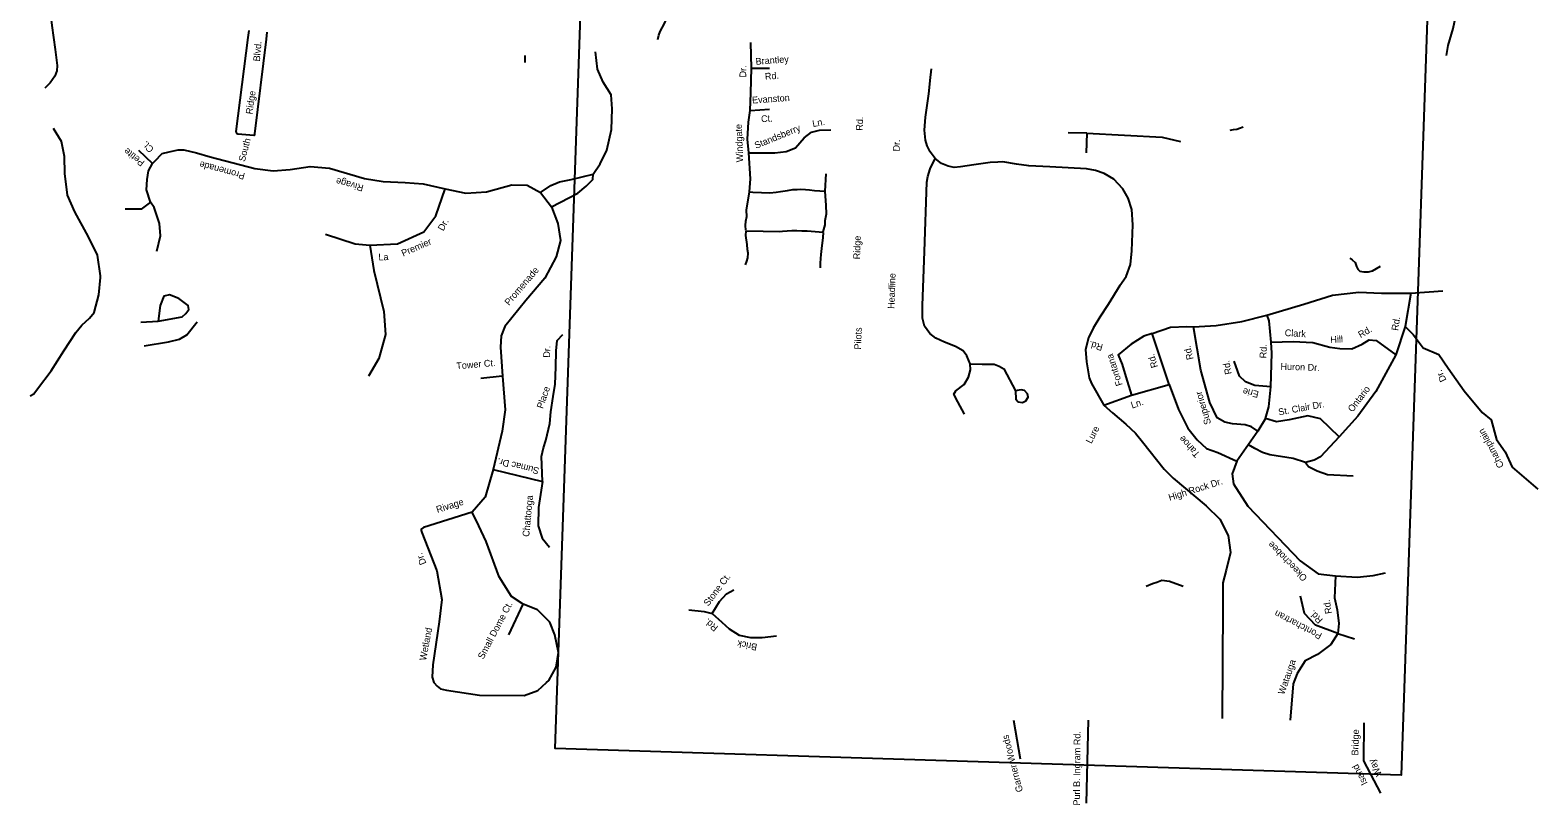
# Model space of a CAD drawing. Extents: x 2308163 to 2335412, y -96774 to 125428.
# Drawn here: x 2321191.5 to 2321648.5, y 52502.5 to 52737.2 of the extents above; entities that cross this region are included whole.
import ezdxf

# ---------------------------------------------------------------- set-up
doc = ezdxf.new("R2010")
doc.units = 0
for name, color, linetype in [('Old_Level_10', 7, 'Continuous'), ('Old_Level_35', 7, 'Continuous'), ('Old_Level_63', 7, 'Continuous')]:
    doc.layers.add(name, color=color, linetype=linetype)

msp = doc.modelspace()

# ---------------------------------------------------------------- linework, layer by layer
at = {"layer": 'Old_Level_35'}
for p, q in [((2321257.61, 52734.96), (2321257.88, 52737.07)), ((2321263.3, 52736.53), (2321263.04, 52734.43)), ((2321341.6, 52727.4), (2321341.53, 52729.52)), ((2321432.45, 52688.45), (2321432.83, 52693.65))]:
    msp.add_line(p, q, dxfattribs=at)
for points in [[(2321381.82, 52734.39), (2321382.04, 52735.64), (2321382.46, 52736.76), (2321383.77, 52739.18), (2321385.41, 52742.99), (2321387.8, 52749.06), (2321390, 52755.31), (2321393.51, 52763.8)], [(2321197.11, 52746.37), (2321197.22, 52745.37), (2321198.07, 52738.63), (2321199.11, 52731.32), (2321199.7, 52726.46), (2321199.64, 52724.83), (2321199.03, 52723.26), (2321197.54, 52721.2), (2321195.98, 52719.62)], [(2321620.88, 52729.51), (2321621.34, 52732.56), (2321622.81, 52737.7), (2321623.65, 52741.57), (2321623.84, 52743.45)], [(2321263.04, 52734.43), (2321259.55, 52705.75), (2321259.53, 52705.48), (2321259.5, 52705.38), (2321259.46, 52705.3), (2321259.39, 52705.27), (2321259.29, 52705.25), (2321254.41, 52705.68), (2321254.22, 52705.79), (2321254.13, 52705.93), (2321254.05, 52706.12), (2321254.02, 52706.27), (2321254, 52706.49), (2321257.61, 52734.96)], [(2321409.58, 52688.15), (2321409.89, 52692.15), (2321409.34, 52700.04), (2321408.98, 52704.19), (2321409.26, 52709.33), (2321409.78, 52712.84), (2321409.97, 52718.19), (2321410.12, 52725.65), (2321409.95, 52733.47)], [(2321349.58, 52683.67), (2321357.54, 52687.82), (2321360.04, 52689.96), (2321362.12, 52691.9), (2321362.18, 52693.52), (2321364.31, 52696.67), (2321366.27, 52700.84), (2321367.7, 52707.05), (2321367.91, 52713.3), (2321367.65, 52717.55), (2321365.16, 52721.47), (2321363.48, 52725.36), (2321362.91, 52730.61)], [(2321410.12, 52725.65), (2321415.58, 52725.66)], [(2321465.81, 52698.28), (2321464.31, 52700.34), (2321463.46, 52702.15), (2321462.91, 52703.87), (2321462.58, 52706.85), (2321462.93, 52710.83), (2321463.93, 52717.86), (2321464.43, 52722.85), (2321464.58, 52724.52), (2321464.69, 52725.45)], [(2321409.78, 52712.84), (2321415.65, 52713.25)], [(2321212.84, 52662.75), (2321211.97, 52668.96), (2321209.2, 52674.54), (2321205.01, 52682.09), (2321202.82, 52687.2), (2321202, 52693.74), (2321201.89, 52698.93), (2321201, 52703.4), (2321198.62, 52707.34)], [(2321409.34, 52700.04), (2321417.26, 52699.97), (2321420.72, 52700.44), (2321423.52, 52701.52), (2321426.15, 52704.56), (2321428.32, 52706.29), (2321430.8, 52706.89), (2321434.22, 52706.96)], [(2321511.82, 52705.95), (2321506.17, 52706.07)], [(2321511.82, 52705.95), (2321511.57, 52700)], [(2321511.82, 52705.95), (2321534.69, 52704.74), (2321540.22, 52703.4)], [(2321555.27, 52706.86), (2321556.31, 52707.06), (2321557.27, 52707.22), (2321558.12, 52707.49), (2321559.2, 52707.91)], [(2321228.64, 52696.76), (2321224.48, 52700.76)], [(2321227.94, 52685.09), (2321226.74, 52688.83), (2321226.99, 52691.93), (2321227.38, 52694.59), (2321228.64, 52696.76), (2321229.26, 52697.48), (2321231.56, 52699.77), (2321233.65, 52700.29), (2321236.34, 52700.94), (2321238.12, 52700.88), (2321241.94, 52700.01), (2321246.05, 52698.83)], [(2321246.05, 52698.83), (2321259.63, 52695.26), (2321265.15, 52694.58), (2321270.34, 52695.01), (2321276.4, 52695.91), (2321282.29, 52695.34), (2321292.9, 52692.27), (2321298.5, 52691.33), (2321305.14, 52690.98), (2321310.67, 52690.67), (2321317.26, 52689.09), (2321323.62, 52687.76), (2321329.79, 52688.16), (2321337.5, 52690.36), (2321342.17, 52690.2), (2321346.16, 52687.97), (2321349.58, 52683.67), (2321351.5, 52678.56), (2321352.31, 52673.48), (2321350.91, 52668.49), (2321347.48, 52662.08), (2321341.71, 52655.27), (2321335.4, 52647.37), (2321334.32, 52644.57), (2321334.08, 52641.14), (2321334.64, 52632.38), (2321335.52, 52622.14), (2321334.56, 52615.65), (2321331.82, 52604.06), (2321329.43, 52595.65), (2321325.46, 52591.11), (2321310.77, 52586.45), (2321310.01, 52585.98), (2321310, 52585.61), (2321310.23, 52584.99), (2321314.75, 52573.39), (2321316.3, 52564.73), (2321315.45, 52557.87), (2321313.52, 52544.89), (2321313.4, 52541.2), (2321313.83, 52539.59), (2321314.9, 52538.44), (2321315.86, 52537.67), (2321317.69, 52537.24), (2321327.73, 52535.66), (2321341.27, 52535.57), (2321345.39, 52537.15), (2321348.06, 52539.51), (2321348.7, 52540.11), (2321350.93, 52544.21), (2321351.7, 52548.62), (2321350.53, 52553.95), (2321349.06, 52557.81), (2321345.25, 52561.51), (2321341, 52563.26), (2321337.38, 52565.6), (2321333.65, 52571.51), (2321329.71, 52582.23), (2321327.53, 52586.98), (2321325.46, 52591.11)], [(2321476.5, 52636.13), (2321475.45, 52638.55), (2321474.36, 52640.02), (2321471.96, 52641.35), (2321468.63, 52642.61), (2321466.01, 52643.87), (2321464.21, 52645.29), (2321462.65, 52647.46), (2321461.97, 52649.88), (2321461.99, 52653.74), (2321462.61, 52670.14), (2321463.34, 52691.08), (2321463.61, 52692.81), (2321464.29, 52695.18), (2321465.81, 52698.28)], [(2321521.83, 52659.78), (2321523.73, 52662.53), (2321525.03, 52666.18), (2321525.41, 52670.32), (2321525.76, 52678.15), (2321525.45, 52682.87), (2321524.39, 52686.28), (2321522.76, 52689.08), (2321519.96, 52692.08), (2321517.11, 52693.75), (2321514.4, 52694.7), (2321511.67, 52695.19), (2321500.63, 52695.81), (2321494.28, 52696.1), (2321490.53, 52696.63), (2321486.39, 52697.24), (2321484.87, 52697.22), (2321482.51, 52697.06), (2321477.52, 52696.42), (2321473.51, 52695.74), (2321471.56, 52695.57), (2321469.78, 52695.95), (2321467.77, 52696.75), (2321465.81, 52698.28)], [(2321346.16, 52687.97), (2321349.34, 52690.13), (2321352, 52691.24), (2321355.46, 52691.93), (2321362.18, 52693.52)], [(2321281.04, 52675.42), (2321290.04, 52672.41), (2321294.46, 52672.01), (2321302.85, 52672.46), (2321310.86, 52676.12), (2321314.47, 52680.92), (2321317.26, 52689.09)], [(2321408.49, 52676.57), (2321408.39, 52677.95), (2321408.44, 52679.33), (2321408.74, 52680.75), (2321408.7, 52682.67), (2321409.58, 52688.15)], [(2321409.58, 52688.15), (2321410.62, 52688.12), (2321413.17, 52687.98), (2321415.73, 52687.89), (2321417.61, 52688.07), (2321419, 52688.27), (2321421.08, 52688.64), (2321422.71, 52688.88), (2321424, 52688.89), (2321425.03, 52689), (2321426.56, 52688.9), (2321427.74, 52688.81), (2321429.26, 52688.61), (2321432.45, 52688.45)], [(2321431.93, 52676.06), (2321432.45, 52678.21), (2321432.49, 52679.48), (2321432.86, 52681.54), (2321432.75, 52684.05), (2321432.45, 52688.45)], [(2321229.95, 52670.21), (2321231, 52674.91), (2321230.68, 52678.62), (2321229.07, 52683.42), (2321227.94, 52685.09), (2321225.2, 52682.96), (2321220.31, 52682.98)], [(2321408.69, 52676.42), (2321418.78, 52676.22), (2321419.52, 52676.29), (2321422.43, 52676.48), (2321423.91, 52676.48), (2321425.44, 52676.38), (2321427.01, 52676.37), (2321431.93, 52676.01)], [(2321294.46, 52672.01), (2321295.68, 52664.34), (2321298.7, 52651.93), (2321299.2, 52645.02), (2321297.22, 52637.71), (2321294.08, 52632.4)], [(2321408.31, 52666.08), (2321408.76, 52667.21), (2321409.04, 52668.18), (2321409.19, 52669.65), (2321408.93, 52670.75), (2321408.84, 52672.28), (2321408.49, 52674.95), (2321408.59, 52676.37)], [(2321431.05, 52665.16), (2321431.1, 52666.58), (2321431.14, 52668), (2321431.25, 52669.19), (2321431.51, 52671), (2321431.92, 52674.38), (2321432.02, 52675.91)], [(2321591.57, 52668.15), (2321592.2, 52667.61), (2321593.12, 52666.74), (2321593.58, 52665.58), (2321593.93, 52664.73), (2321594.56, 52664.17), (2321595.74, 52663.94), (2321597.15, 52663.93), (2321598.42, 52664.31), (2321600.8, 52665.64)], [(2321191.51, 52626.42), (2321192.63, 52627.02), (2321193.75, 52628.53), (2321197.84, 52633.98), (2321201.69, 52640.06), (2321205.35, 52645.58), (2321207.15, 52647.77), (2321209.51, 52649.97), (2321210.87, 52651.67), (2321212.35, 52656.98), (2321212.83, 52662.23), (2321212.84, 52662.75)], [(2321521.83, 52659.78), (2321518.26, 52654.02), (2321515.77, 52650.26), (2321513.77, 52646.87), (2321512.32, 52643.94), (2321511.44, 52640.45), (2321511.69, 52636.68), (2321512.53, 52631.88), (2321513.22, 52630.09), (2321516.99, 52623.54), (2321519.57, 52621.21), (2321523.6, 52617.81), (2321526.52, 52615.07), (2321528.69, 52612.49), (2321535.22, 52604.21), (2321537.95, 52601.44), (2321548.02, 52593.1), (2321552.12, 52589.03), (2321554.61, 52584.08), (2321555.38, 52578.88), (2321554.09, 52573.59), (2321553.02, 52569.7), (2321553.09, 52562.64), (2321552.83, 52528.67)], [(2321610.04, 52657.45), (2321619.7, 52658.17)], [(2321225.03, 52648.72), (2321230.31, 52649.01), (2321237.58, 52650.37), (2321238.69, 52651.3), (2321239.6, 52652.53), (2321239.43, 52653.81), (2321236.54, 52655.85), (2321233.76, 52657.04), (2321232.06, 52656.57), (2321230.92, 52653.79)], [(2321230.92, 52653.79), (2321230.31, 52649.01)], [(2321531.58, 52645.28), (2321537.16, 52647.15), (2321542.15, 52647.43), (2321544.12, 52647.3), (2321550.97, 52647.7), (2321558.8, 52648.96), (2321566.33, 52650.8), (2321577.64, 52654.14), (2321586.31, 52656.94), (2321594.29, 52657.78), (2321601.1, 52657.53), (2321610.04, 52657.45)], [(2321610.04, 52657.45), (2321608.32, 52647.43), (2321605.48, 52638.78), (2321599.4, 52627.67), (2321593.92, 52620.26), (2321588.26, 52613.95), (2321582.64, 52607.86), (2321580.77, 52606.87), (2321578.09, 52606.18), (2321574.35, 52607.39), (2321567.31, 52608.49), (2321565.06, 52609.18), (2321562.79, 52610.41), (2321560.77, 52611.56)], [(2321567.71, 52642.61), (2321567.06, 52649.08), (2321566.5, 52650.85)], [(2321226.06, 52641.54), (2321233.48, 52642.8), (2321236.81, 52643.56), (2321239.01, 52644.9), (2321242.16, 52648.81)], [(2321346.77, 52600.43), (2321346.52, 52608.01), (2321347.12, 52610.68), (2321347.87, 52612.84), (2321349.05, 52618.01), (2321349.34, 52621.53), (2321350.01, 52626.22), (2321350.64, 52629.9), (2321350.82, 52635.11), (2321350.99, 52639.98), (2321351.27, 52643.16), (2321353.01, 52644.95)], [(2321536.81, 52629.84), (2321531.58, 52645.28), (2321529.07, 52644.46), (2321525.3, 52642.08), (2321521.34, 52638.85), (2321522.5, 52635.9), (2321523.62, 52632.1), (2321525.31, 52626.55)], [(2321563.68, 52615.67), (2321561.69, 52617.03), (2321559.82, 52617.65), (2321555.93, 52617.91), (2321553.63, 52618.4), (2321551.37, 52619.77), (2321549.07, 52624.41), (2321546.42, 52634.12), (2321544.12, 52647.3)], [(2321608.32, 52647.43), (2321610.71, 52644.96), (2321613.78, 52640.96), (2321618.53, 52638.96), (2321621.36, 52634.74), (2321626.17, 52627.93), (2321631.68, 52621.33), (2321634.35, 52619.17), (2321635.98, 52613.16), (2321638.6, 52609.4), (2321640.73, 52604.75), (2321648.53, 52598.07)], [(2321588.26, 52613.95), (2321582.6, 52619.45), (2321578.85, 52620.3), (2321573.11, 52619.14), (2321569.27, 52618.53), (2321566.01, 52619.51), (2321567.03, 52623.02), (2321567.56, 52629.09), (2321567.94, 52639.35), (2321567.71, 52642.61)], [(2321567.71, 52642.61), (2321574.34, 52642.84), (2321580.36, 52642.5), (2321585.47, 52641.1), (2321588.51, 52640.72), (2321592.11, 52640.67), (2321595.28, 52642.05), (2321597.36, 52643.34), (2321599.52, 52643.19), (2321605.48, 52638.78)], [(2321474.72, 52620.88), (2321472.71, 52624.59), (2321471.53, 52626.89), (2321472.07, 52627.87), (2321474.65, 52629.79), (2321475.98, 52632.01), (2321476.56, 52634.25), (2321476.5, 52636.13)], [(2321476.5, 52636.13), (2321480.12, 52636.02), (2321483.7, 52635.94), (2321485.29, 52635.42), (2321486.63, 52634.56), (2321490.15, 52627.89), (2321490.28, 52625.38), (2321490.98, 52624.6), (2321492.28, 52624.35), (2321493.37, 52624.9), (2321494.06, 52625.96), (2321493.82, 52626.95), (2321492.88, 52628.01), (2321491.91, 52628.21), (2321490.65, 52628.04), (2321490.15, 52627.89)], [(2321567.56, 52629.09), (2321562.75, 52629.51), (2321559.92, 52630.66), (2321558.13, 52632.38), (2321556.5, 52636.87)], [(2321328.16, 52631.78), (2321334.63, 52632.48)], [(2321516.99, 52623.54), (2321525.31, 52626.55)], [(2321525.31, 52626.55), (2321536.81, 52629.84)], [(2321536.81, 52629.84), (2321539.59, 52622.21), (2321542.38, 52616.62), (2321545.24, 52613.08), (2321548.13, 52610.46), (2321551.52, 52609.2), (2321557.24, 52606.57)], [(2321566.01, 52619.51), (2321563.68, 52615.67), (2321557.24, 52606.57), (2321555.88, 52602.73), (2321556.24, 52599.74), (2321560.59, 52592.94), (2321576.52, 52576.36), (2321581.89, 52572.5), (2321587.15, 52571.87), (2321593.78, 52571.41), (2321598.61, 52571.93), (2321602.31, 52572.72)], [(2321331.82, 52604.06), (2321346.77, 52600.43), (2321345.65, 52592.57), (2321345.46, 52587.02), (2321346.68, 52583.28), (2321348.94, 52580.51)], [(2321578.09, 52606.18), (2321579, 52605.02), (2321581.61, 52603.67), (2321584.81, 52602.54), (2321592.55, 52602.15)], [(2321587.15, 52571.87), (2321586.92, 52565.23), (2321587.71, 52561.54), (2321588.25, 52557.39), (2321587.92, 52554.43), (2321585.74, 52551.07), (2321581.74, 52548), (2321578, 52546.06), (2321575.58, 52542.25), (2321574.32, 52539.09), (2321573.48, 52528.1)], [(2321398.23, 52560.46), (2321400.45, 52564.09), (2321402.62, 52566.42), (2321404.76, 52567.64)], [(2321529.76, 52568.72), (2321531.74, 52569.57), (2321533.04, 52569.98), (2321534.55, 52570.51), (2321536.88, 52570.2), (2321541, 52568.77)], [(2321336.58, 52554.03), (2321341, 52563.26)], [(2321587.92, 52554.43), (2321581.13, 52556.86), (2321577.81, 52560.41), (2321576.62, 52565.72)], [(2321391.18, 52561.51), (2321395.83, 52561.03), (2321398.23, 52560.46), (2321401.2, 52557.78), (2321403.38, 52555.78), (2321406.38, 52553.9), (2321409.89, 52553.14), (2321413.44, 52553.18), (2321417.76, 52553.72)], [(2321587.92, 52554.43), (2321592.91, 52552.79)], [(2321491.74, 52516.32), (2321489.65, 52528.03)], [(2321511.68, 52503.03), (2321512.3, 52528.17)], [(2321600.92, 52506), (2321595.76, 52515.81), (2321595.92, 52527.37)]]:
    msp.add_lwpolyline(points, dxfattribs=at)
at = {"layer": 'Old_Level_63'}
msp.add_lwpolyline([(2321621.26, 52922.18), (2321607.1, 52511.43), (2321350.69, 52519.52), (2321367.22, 52998.81)], dxfattribs=at)

# ---------------------------------------------------------------- texts
at = {"layer": 'Old_Level_10'}
for s, height, rotation, p in [('Blvd.', 2.051, 85.2272, (2321261.15, 52727.64)), ('Brantley', 2.051, 4.3646, (2321411.49, 52726.67)), ('Dr.', 2.051, 89.4385, (2321408.56, 52722.84)), ('Rd.', 2.051, 4.3646, (2321414.31, 52722.14)), ('Ridge', 2.051, 81.8623, (2321258.87, 52711.59)), ('Evanston', 2.051, 3.9715, (2321410.4, 52714.95)), ('Windgate', 2.051, 92.2238, (2321407.66, 52697.21)), ('Ct.', 2.051, 3.9715, (2321413.13, 52709.26)), ('Ln.', 2.051, 10.8306, (2321428.81, 52707.82)), ('Rd.', 2.051, 87.9298, (2321443.86, 52706.69)), ('South ', 2.051, 75.4775, (2321256.59, 52697.21)), ('Standsberry', 2.0505, 22.4236, (2321411.58, 52701.19)), ('Petite', 2.051, 141.9823, (2321226.4, 52697.35)), ('Ct.', 2.051, 134.3578, (2321229.16, 52701.25)), ('Dr.', 2.051, 87.0673, (2321455.05, 52700.39)), ('Promenade', 2.051, 164.8185, (2321256.78, 52693.83)), ('Rivage ', 2.051, 164.9249, (2321292.74, 52690.24)), ('Dr.', 2.051, 61.5716, (2321316.74, 52676.17)), ('Premier ', 2.051, 23.573, (2321304.57, 52668.56)), ('Ridge', 2.051, 88.0247, (2321443.05, 52667.72)), ('La ', 2.051, 2.8628, (2321297.13, 52667.39)), ('Promenade', 2.051, 49.5056, (2321336.66, 52653.6)), ('Headline', 2.051, 88.0247, (2321453.49, 52652.72)), ('Rd.', 2.051, 80.9562, (2321606.15, 52646.02)), ('Pilots', 2.051, 87.8633, (2321443.35, 52640.39)), ('Clark', 2.051, 356.6269, (2321571.76, 52644.51)), ('Hill', 2.051, 3.1309, (2321585.69, 52642.39)), ('Rd.', 2.051, 29.8603, (2321594.79, 52643.84)), ('Dr.', 2.051, 87.4369, (2321349.04, 52637.9)), ('Rd.', 2.051, 164.5659, (2321516.85, 52641.95)), ('Rd.', 2.051, 103.6352, (2321544.16, 52637.57)), ('Rd.', 2.051, 87.8778, (2321566.22, 52637.72)), ('Tower Ct.', 2.051, 4.9538, (2321320.77, 52634.42)), ('Fontana', 2.051, 107.7984, (2321522.69, 52629.74)), ('Rd.', 2.051, 106.6838, (2321533.39, 52635.19)), ('Rd.', 2.051, 101.3226, (2321555.77, 52633.08)), ('Huron Dr.', 2.051, 358.0247, (2321570.49, 52634.32)), ('Dr.', 2.051, 116.2723, (2321620.89, 52631.2)), ('Place', 2.051, 71.0915, (2321346.92, 52622.35)), ('Superior', 2.051, 106.4077, (2321549.51, 52618.01)), ('Erie', 2.051, 167.3506, (2321564.09, 52627.75)), ('Ontario', 2.051, 52.5914, (2321592.36, 52621.29)), ('Ln.', 2.051, 18.5093, (2321525.56, 52622.52)), ('St. Clair Dr.', 2.0505, 10.3937, (2321570.07, 52620.43)), ('Lure', 2.051, 62.5274, (2321513.19, 52611.72)), ('Tahoe', 2.051, 132.3947, (2321546.27, 52608.81)), ('Champlain', 2.051, 118.4032, (2321638.34, 52605.17)), ('Sumac Dr.', 2.051, 166.5432, (2321345.95, 52604.57)), ('High Rock Dr.', 2.0505, 17.5209, (2321536.93, 52594.55)), ('Rivage ', 2.051, 17.4763, (2321314.96, 52590.89)), ('Chattooga', 2.051, 84.5243, (2321342.76, 52583.6)), ('Okeechobee', 2.051, 134.2898, (2321578.78, 52571.38)), ('Dr.', 2.051, 112.2366, (2321311.65, 52575.65)), ('Stone Ct.', 2.051, 52.9539, (2321397.08, 52562.5)), ('Small Dome Ct.', 2.0505, 62.207, (2321328.87, 52546.41)), ('Rd.', 2.051, 99.3895, (2321586.13, 52560.5)), ('Rd.', 2.051, 140.7679, (2321400.23, 52556.41)), ('Pontchartran', 2.0505, 152.5317, (2321583.28, 52554.29)), ('Rd.', 2.051, 134.4566, (2321583.49, 52558.59)), ('Wetland', 2.051, 79.2672, (2321311.51, 52546.07)), ('Brick', 2.051, 169.0975, (2321412.02, 52551.18)), ('Watauga', 2.051, 70.8529, (2321571.62, 52535.71)), ('Garner Woods', 2.0505, 104.4911, (2321492.48, 52506.61)), ('Purl B. Ingram Rd.', 2.0505, 89.5734, (2321509.73, 52502.25)), ('Bridge', 2.051, 88.4171, (2321594.09, 52517.4)), ('Isand', 2.051, 117.301, (2321596.99, 52509.03)), ('Way', 2.051, 117.301, (2321601.36, 52511.73))]:
    msp.add_text(s, height=height, rotation=rotation, dxfattribs=at).set_placement(p)

doc.saveas('drawing.dxf')
